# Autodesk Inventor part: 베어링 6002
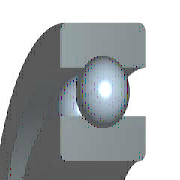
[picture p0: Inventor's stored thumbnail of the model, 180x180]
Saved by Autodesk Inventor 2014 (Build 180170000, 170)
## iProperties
Created: 2012-02
Part Number: 베어링 6002
Material: 강철, 연강
Description: 깊은 그루브 볼 베어링
Document SubType Name: Modeling
Standard: KS B 2023
Designer: mduedu
Standards Organization: KS
Language: ko-KR
Size Designation: 6002 - 15 x 32 x 9
Categories: <MemberInstance><Categories><Category DisplayName="샤프트 부품" InternalName="7f7aeb1f-a693-4053-b835-cee3144e0d98" Mnemonic="SHFT"><Category DisplayName="베어링" Inter
Density: 7.86 g/cm^3
Mass: 29.8124 g
Surface Area: 39.9079 cm^2
Volume: 3.79293 cm^3
Appearance: 분홍색
IsCustomPart: 1
Author: mduedu
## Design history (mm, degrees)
sketch "스케치" dims "d0" = 4.42 (= -0.26 x WD + 0.26 x BD)
  geometry: L1 (2.29, 11.75)-(6.71, 11.75); L2 (4.5, 11.75)-(4.5, 9.54); L3 (4.5, 11.75)-(4.5, 13.96); L4 (2.858, 10.271)-(0, 10.271); L5 (0, 7.5)-(9, 7.5); L6 (2.858, 13.229)-(0, 13.229); L7 (0, 16)-(9, 16); L8 (9, 7.5)-(9, 10.271); L9 (6.142, 10.271)-(9, 10.271); L10 (6.142, 13.229)-(9, 13.229); L11 (9, 16)-(9, 13.229); L12 (-1.4, 0)-(8.4, 0) reference; L13 (0, -0.3)-(0, 5.3) reference
  constraints: 22 end point, 4 point on line, 2 collinear, 2 perpendicular, 2 symmetric about line, 1 midpoint, 1 parallel, 14 other
  dimensions: "d9" = 15 diameter of L5 L12 (= WD); "d11" = 32 diameter of L7 L12 (= BD); "d12" = 9 distance between parallel lines of L8 L13 (= KB); "d13" = 20.542 diameter of L9 L12 (= 0.326 x BD + 0.674 x WD)
revolve "본체" stored, may be unused: angle "d6" = 90 deg
revolve "볼" stored, may be unused: angle "d7" = 90 deg
pattern_circular "IDS_ARRAYBALL[SIMPL:T]" dims angle "d3" = 360 deg
body "Solid1"
fillet "모깎기1" dims "d1" = 0.3 (= KRS)
other parameters: "WD" = 15 [user parameter; used in 5 equation terms], "BD" = 32 [user parameter; used in 5 equation terms], "KB" = 9 [user parameter; used in 1 equation term], "KRS" = 0.3 [user parameter; used in 1 equation term], "d4" = 0, "d5" = 0, "d8" = 0, "d14" = 0, "d15" = 0, "BBA" = 0 [user parameter], "BC0" = 2850000 [user parameter], "BC" = 5590000 [user parameter], "BR" = 16 (= 0.5 x BD) [user parameter], "WR" = 7.5 (= 0.5 x WD) [user parameter]
